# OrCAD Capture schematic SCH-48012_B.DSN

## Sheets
1 01 COVER: title: AUD-EXP-42448; rev: B; company: NXP Semiconductors; note: SCH-48012, PDF: SPF-48012; note: 6501 William Cannon Drive West; note: Austin, TX 78735-8598
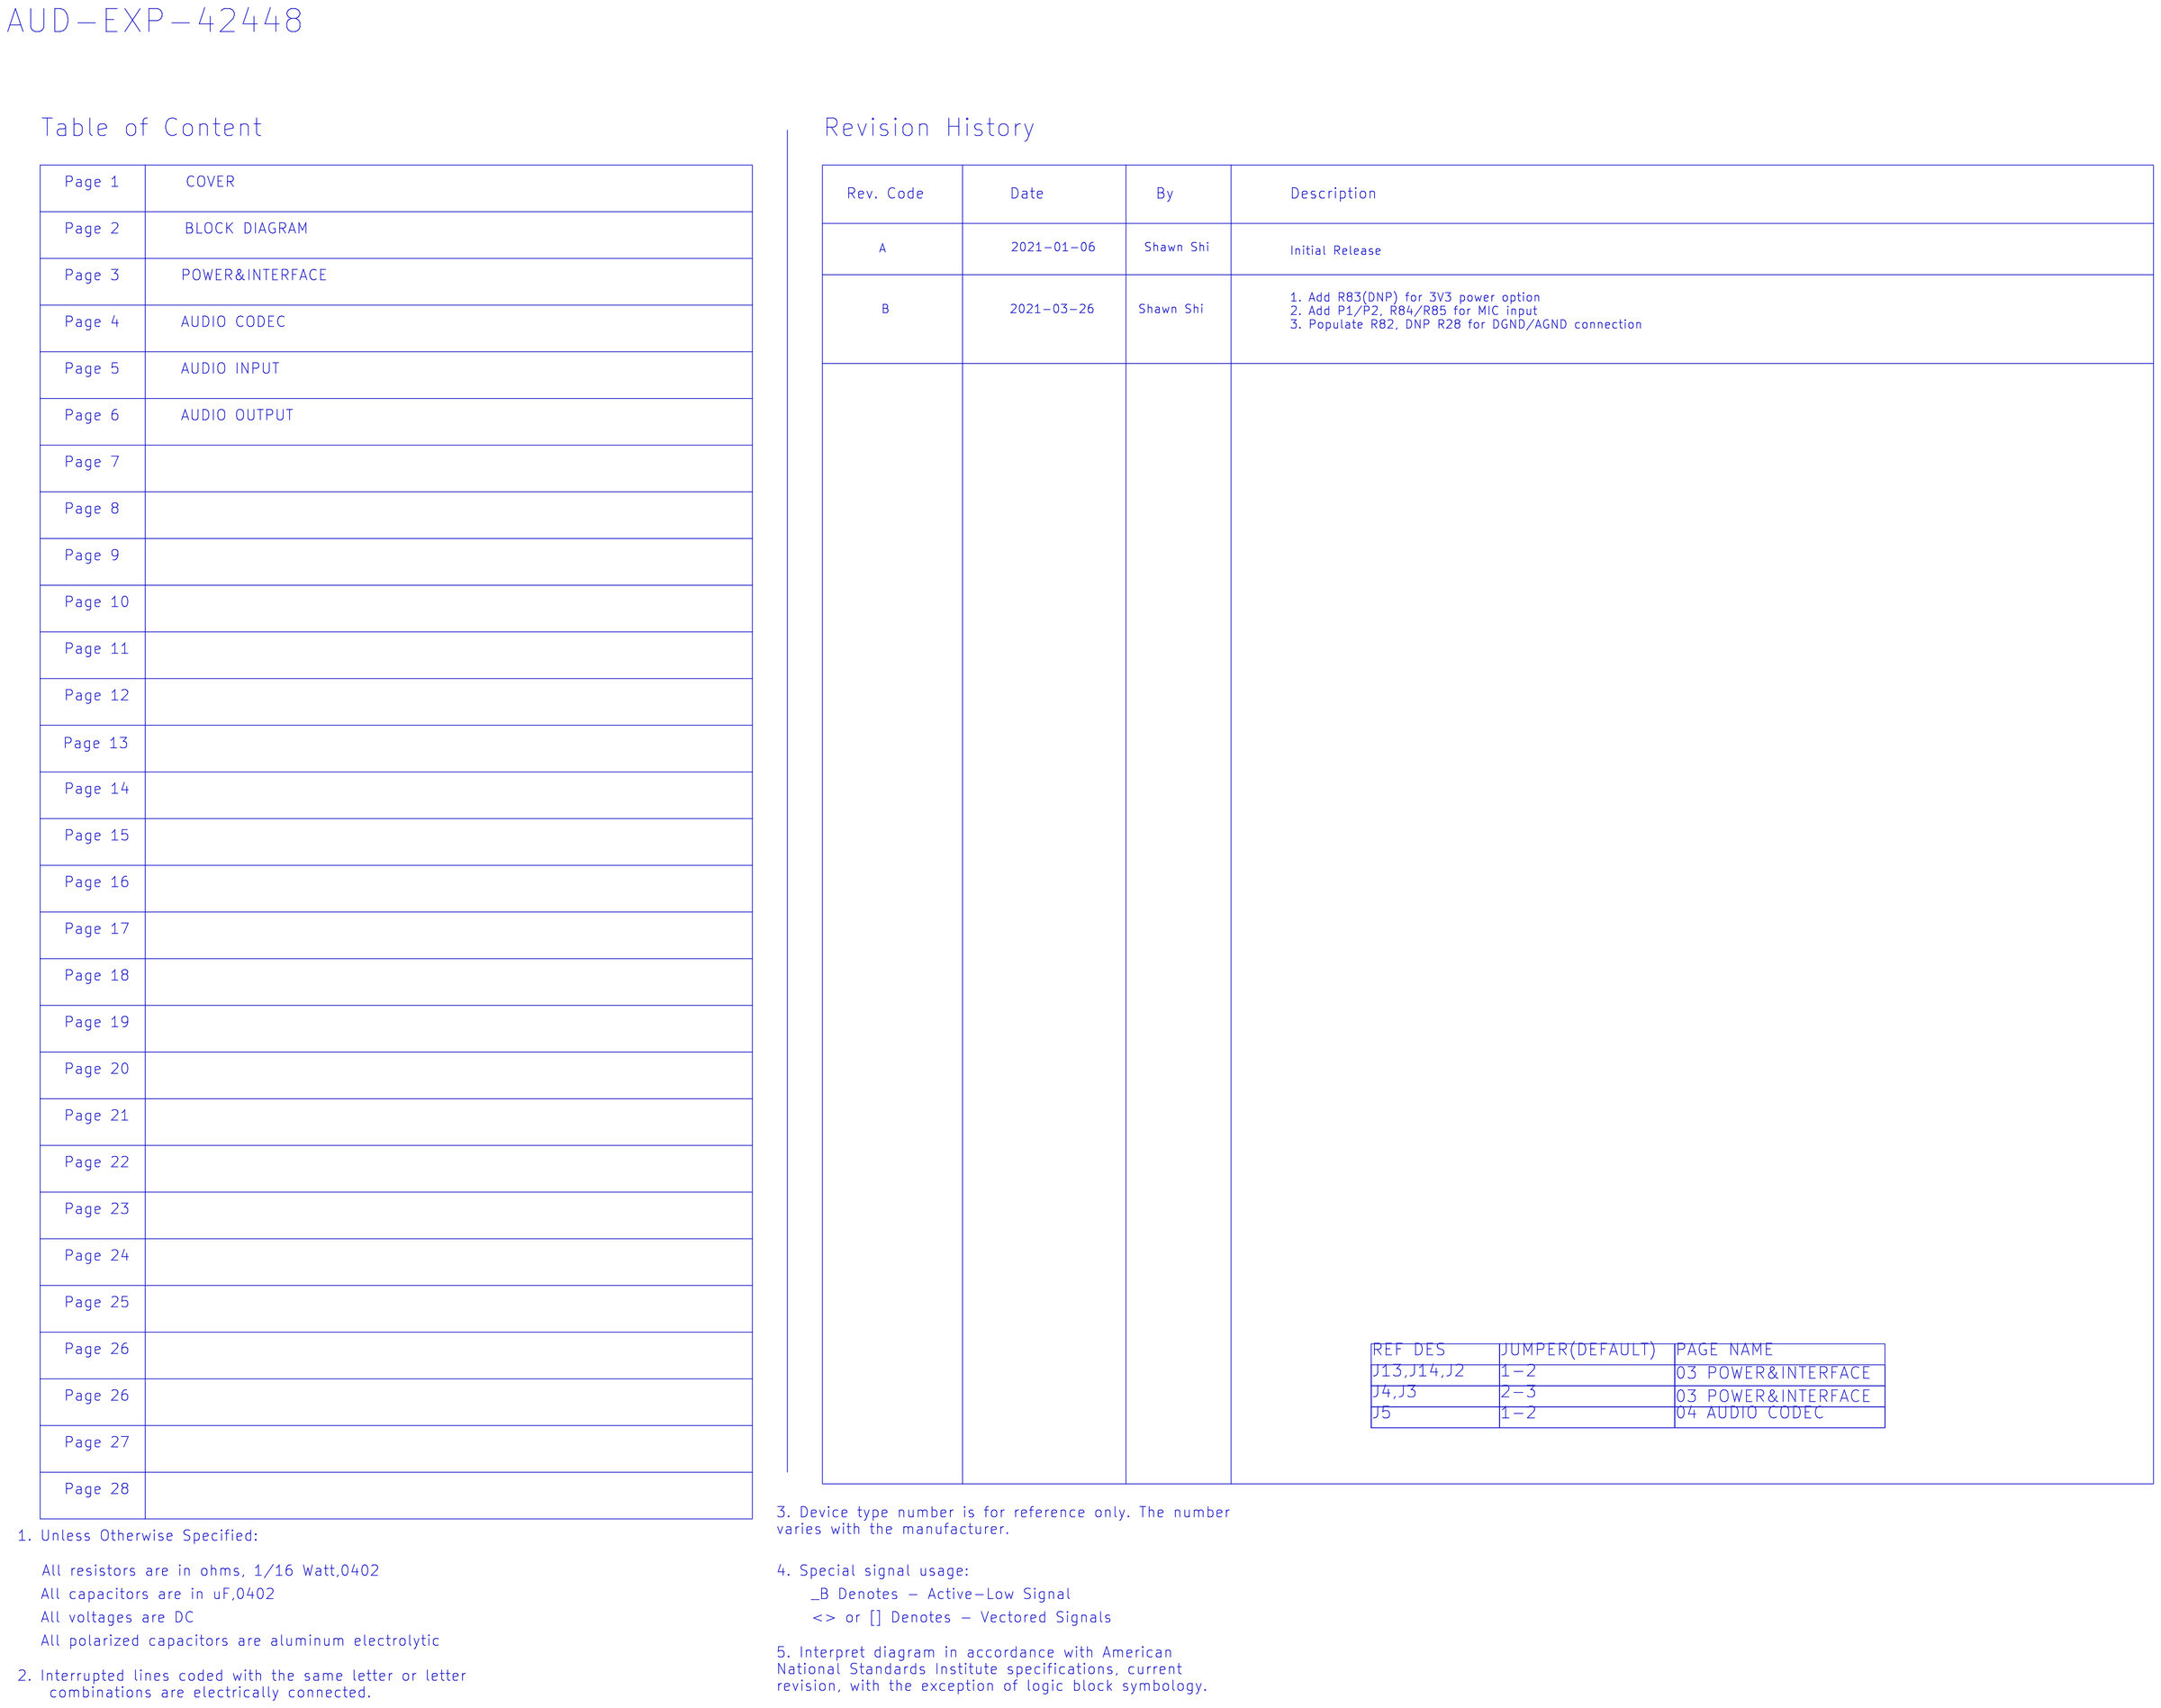
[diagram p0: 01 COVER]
2 02 BLOCK DIAGRAM
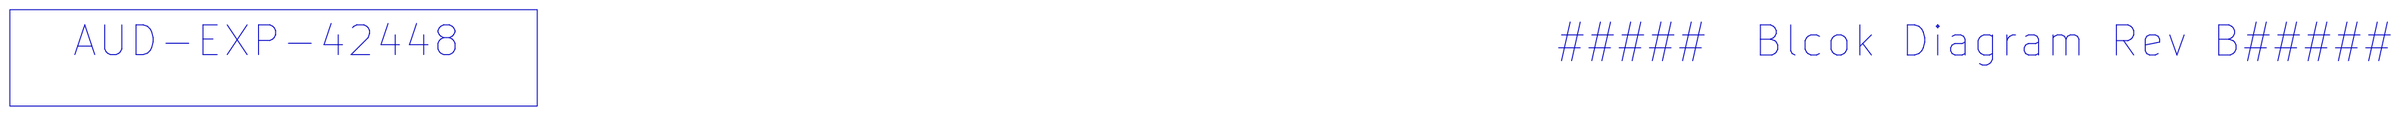
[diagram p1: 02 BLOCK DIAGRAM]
3 03 POWER&INTERFACE: size C
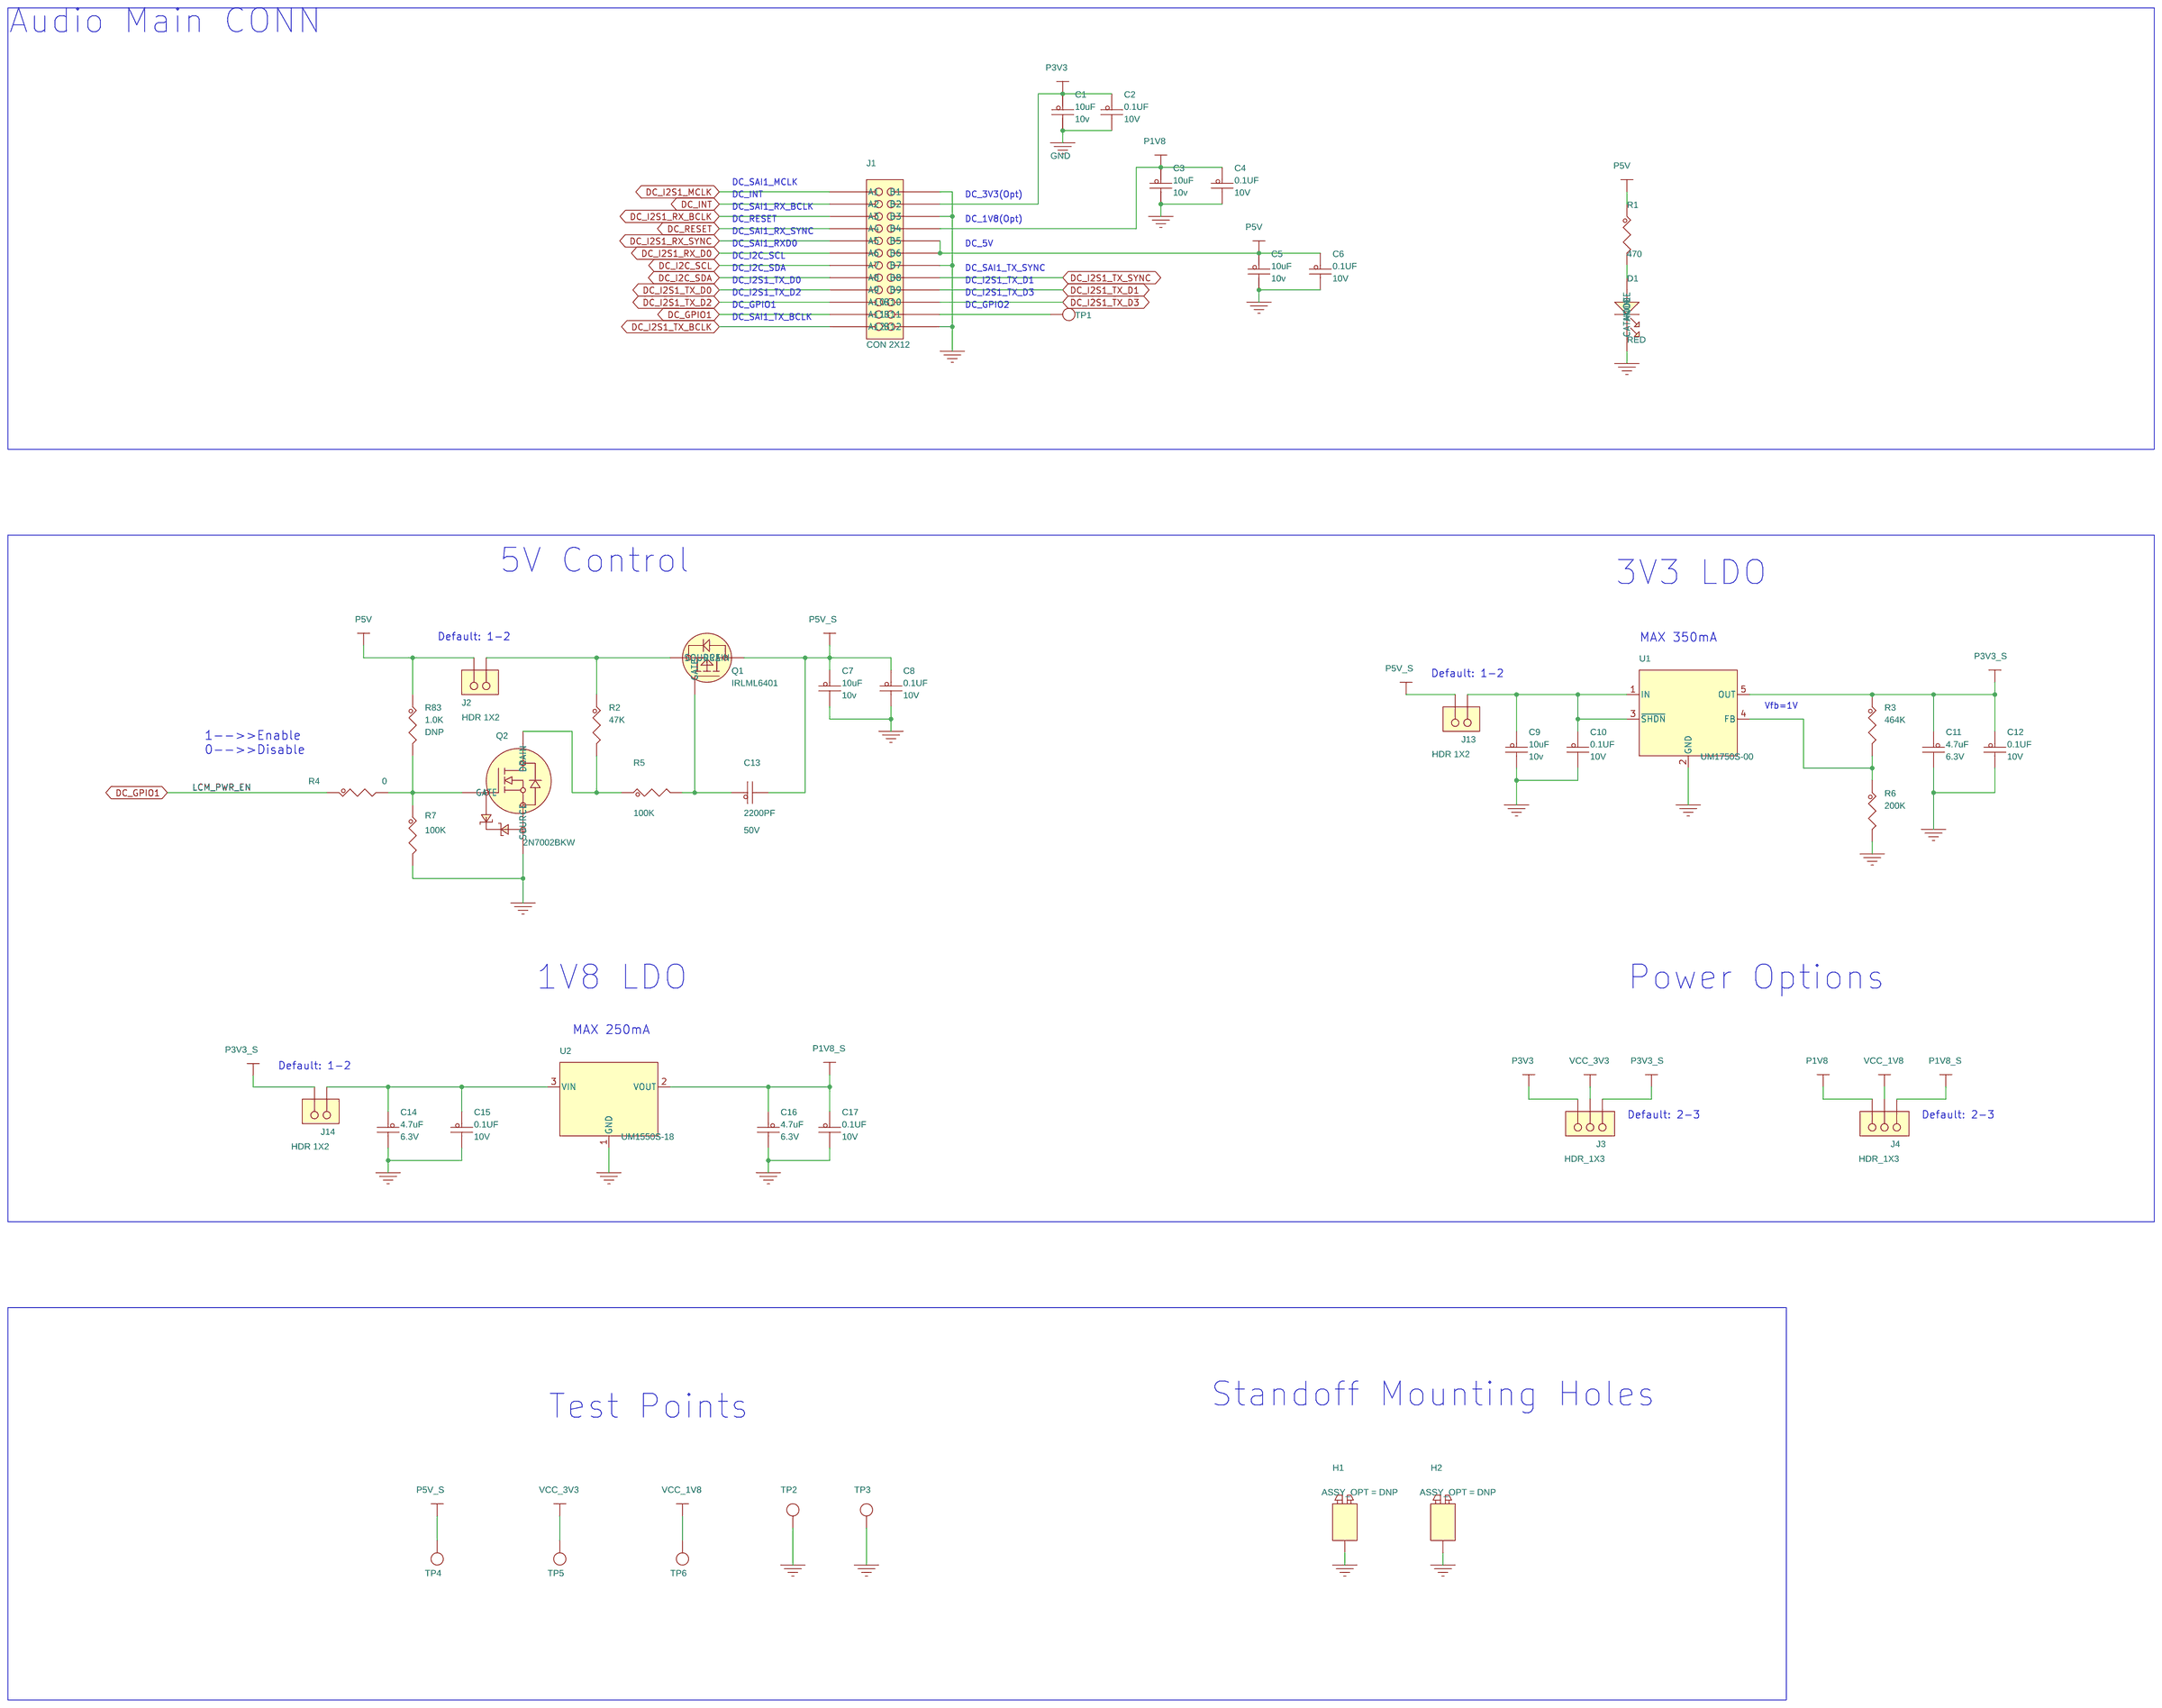
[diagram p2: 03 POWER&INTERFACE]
4 04 AUDIO CODEC: size C
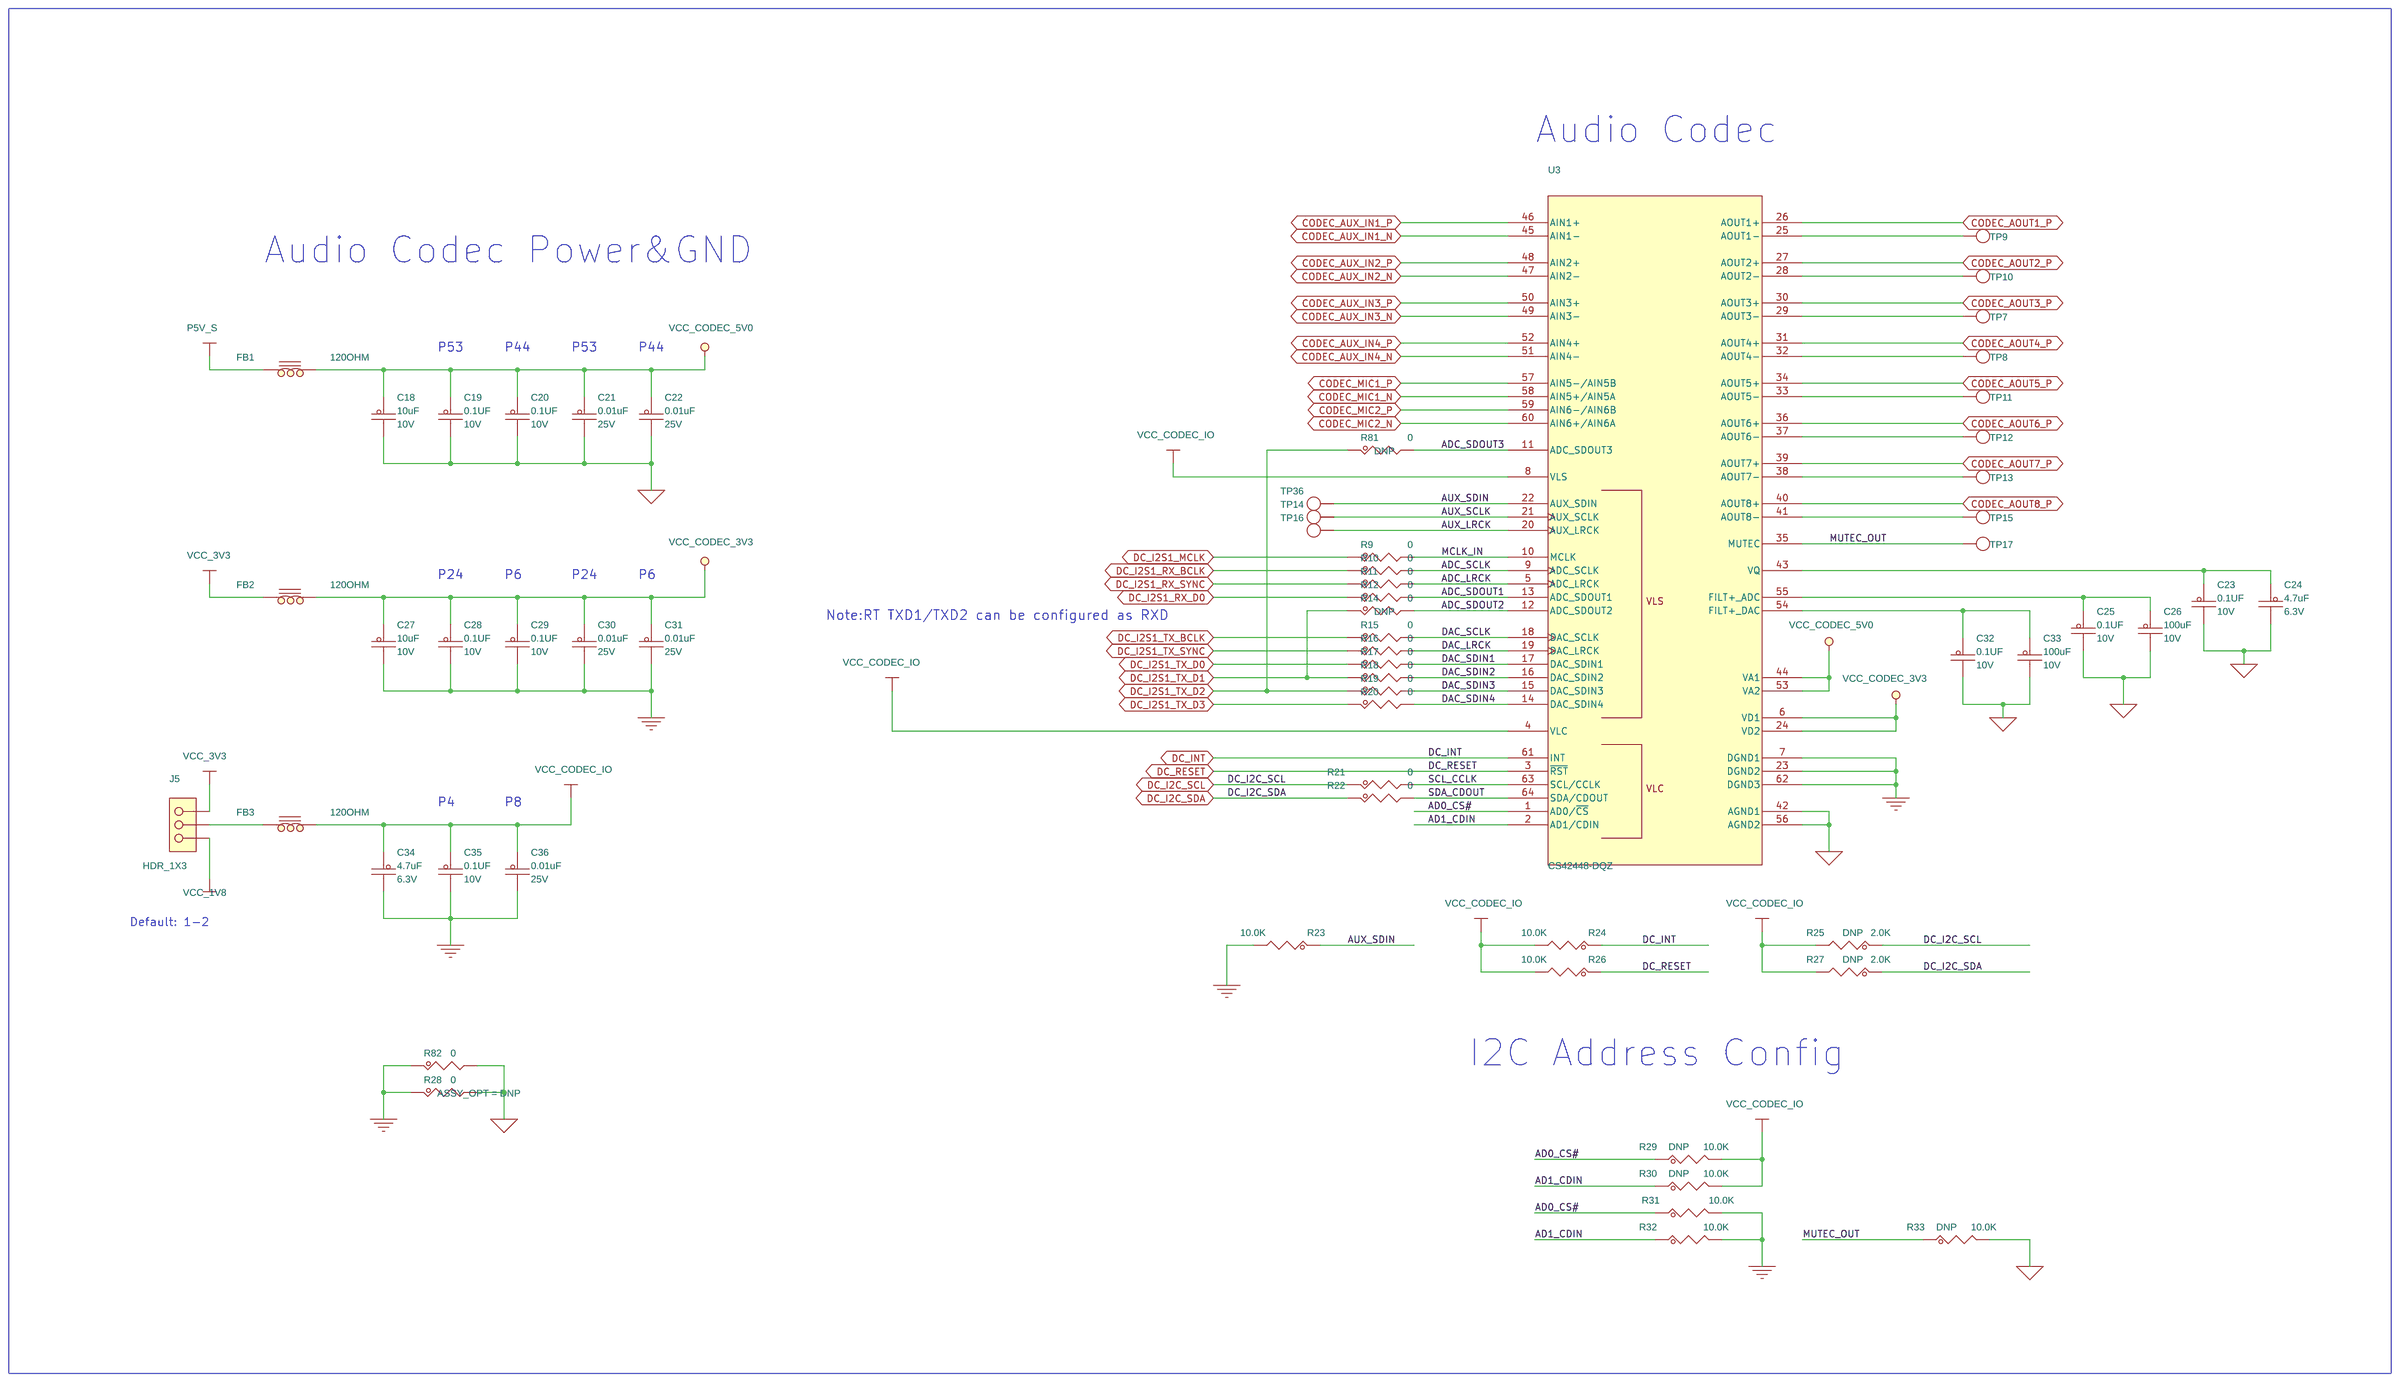
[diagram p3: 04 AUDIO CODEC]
5 05 AUDIO INPUT: size C
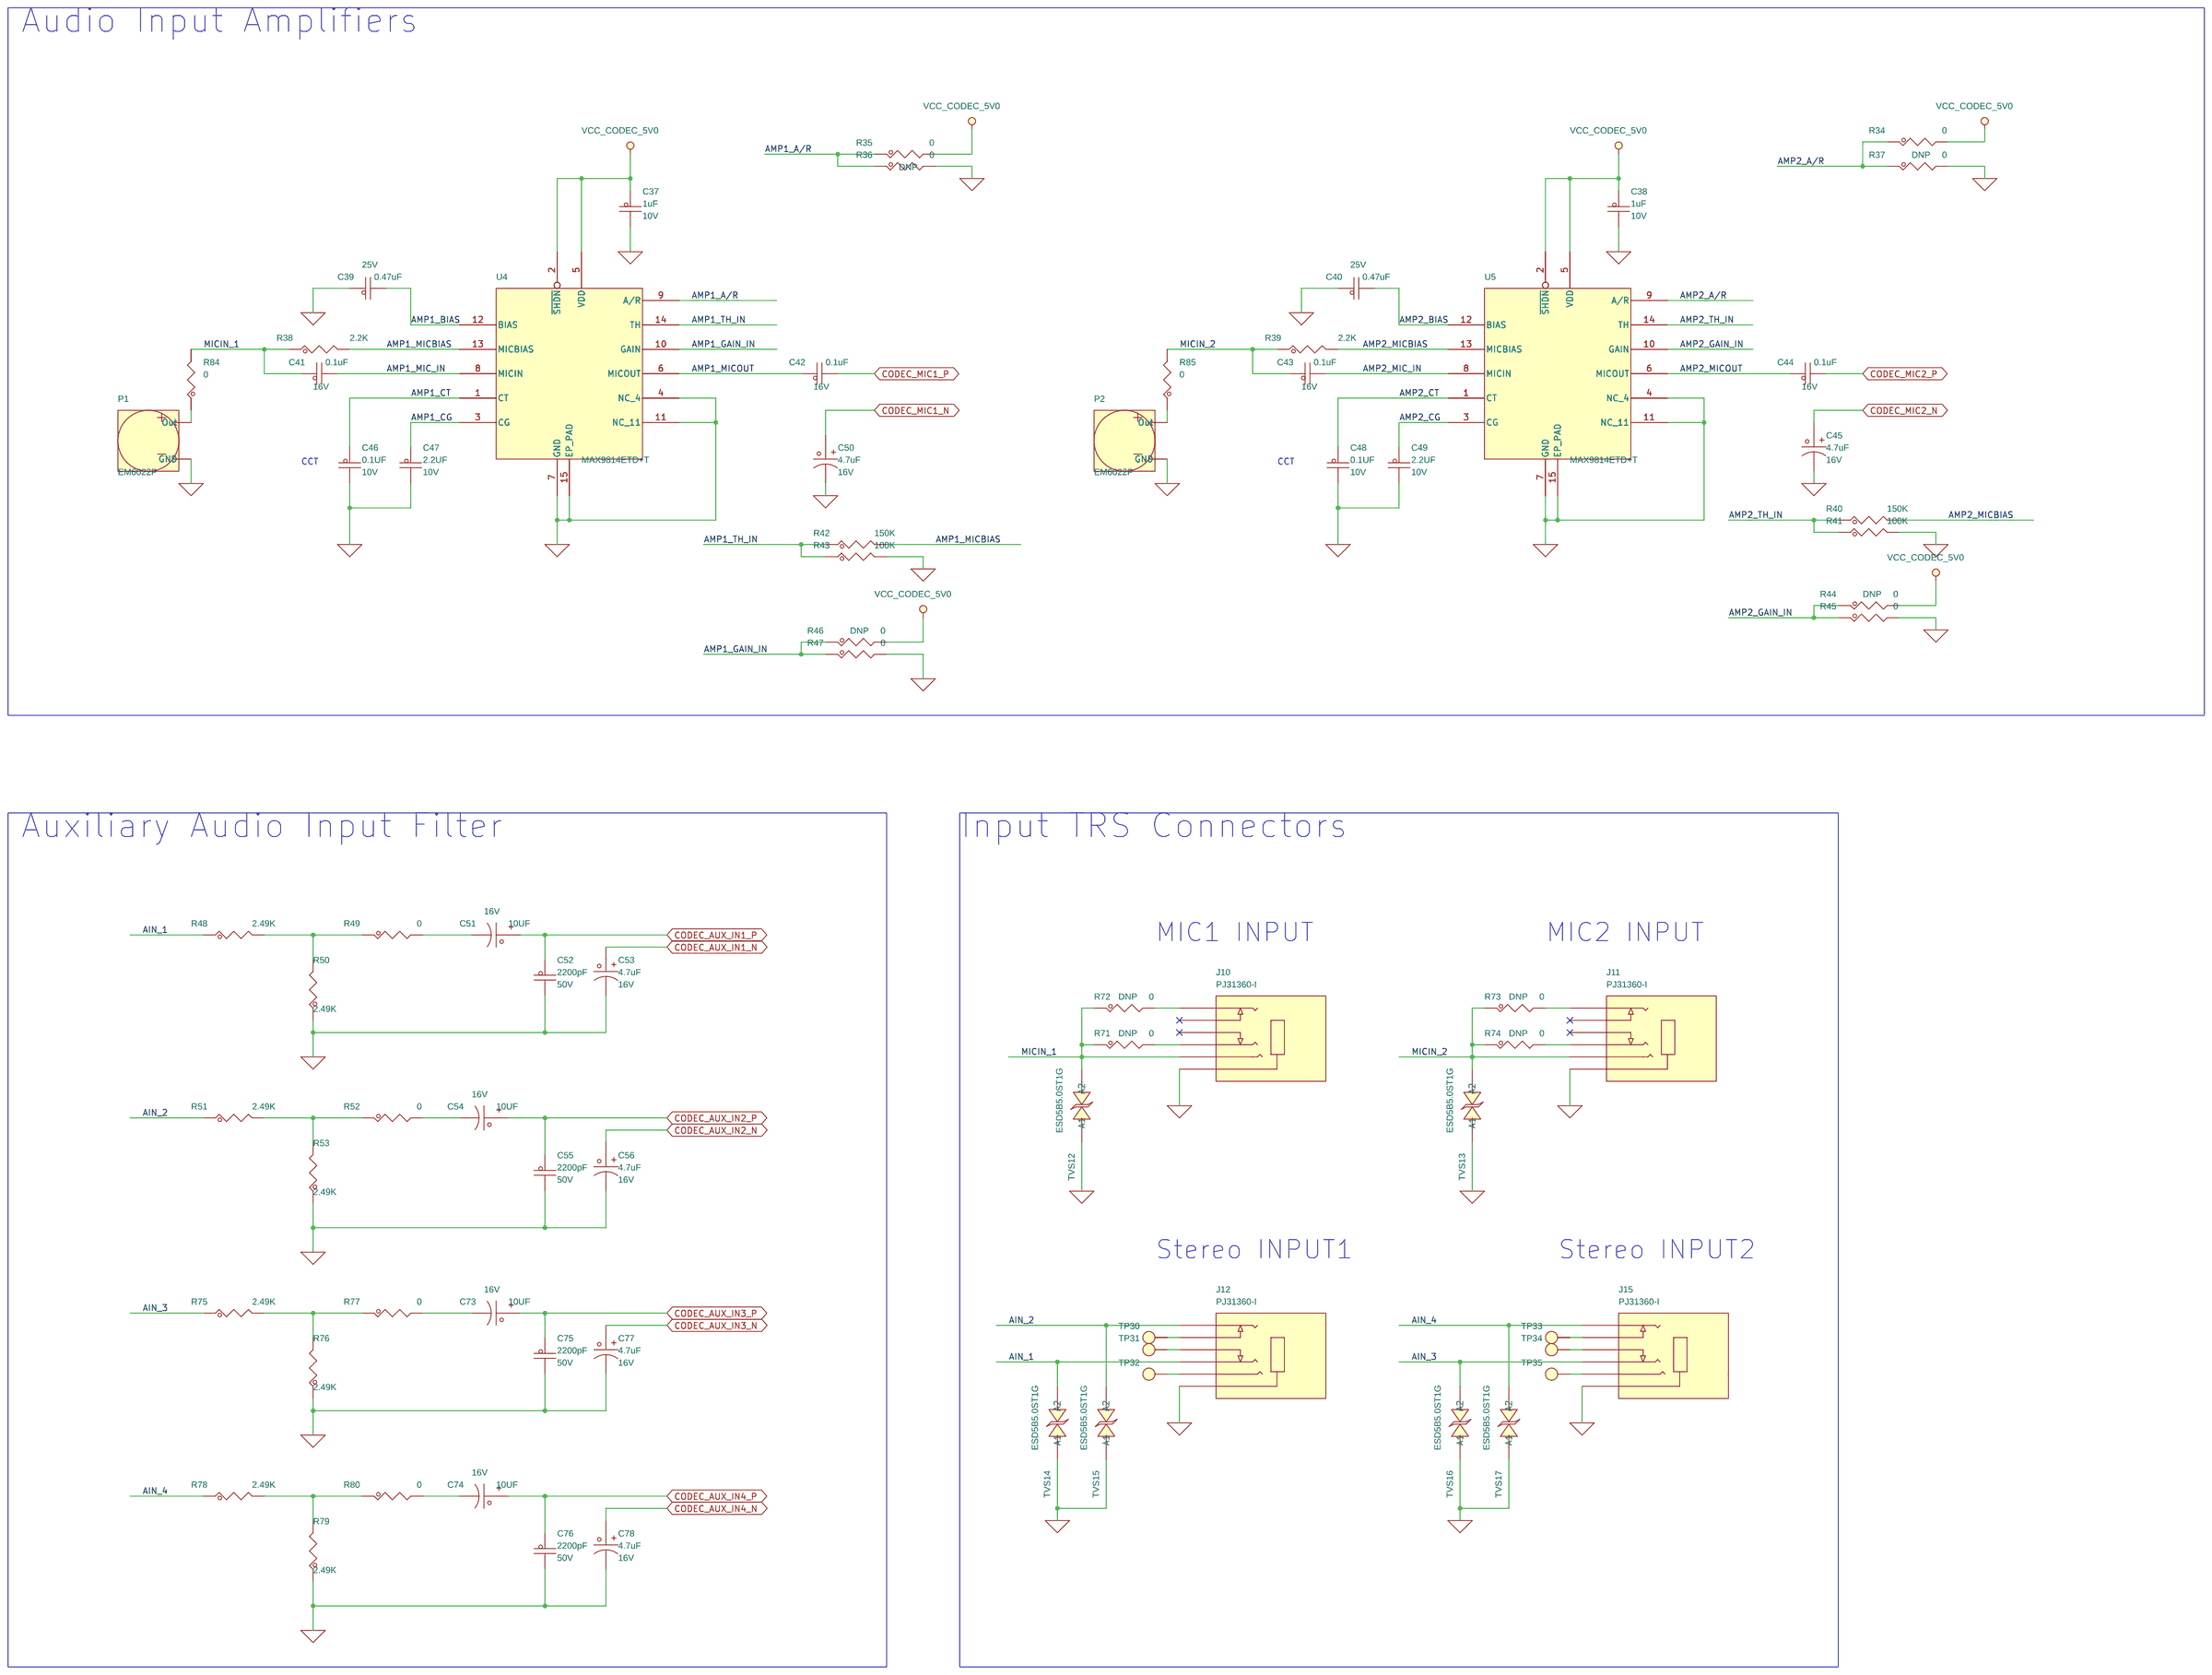
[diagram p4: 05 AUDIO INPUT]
6 06 AUDIO OUTPUT: size C
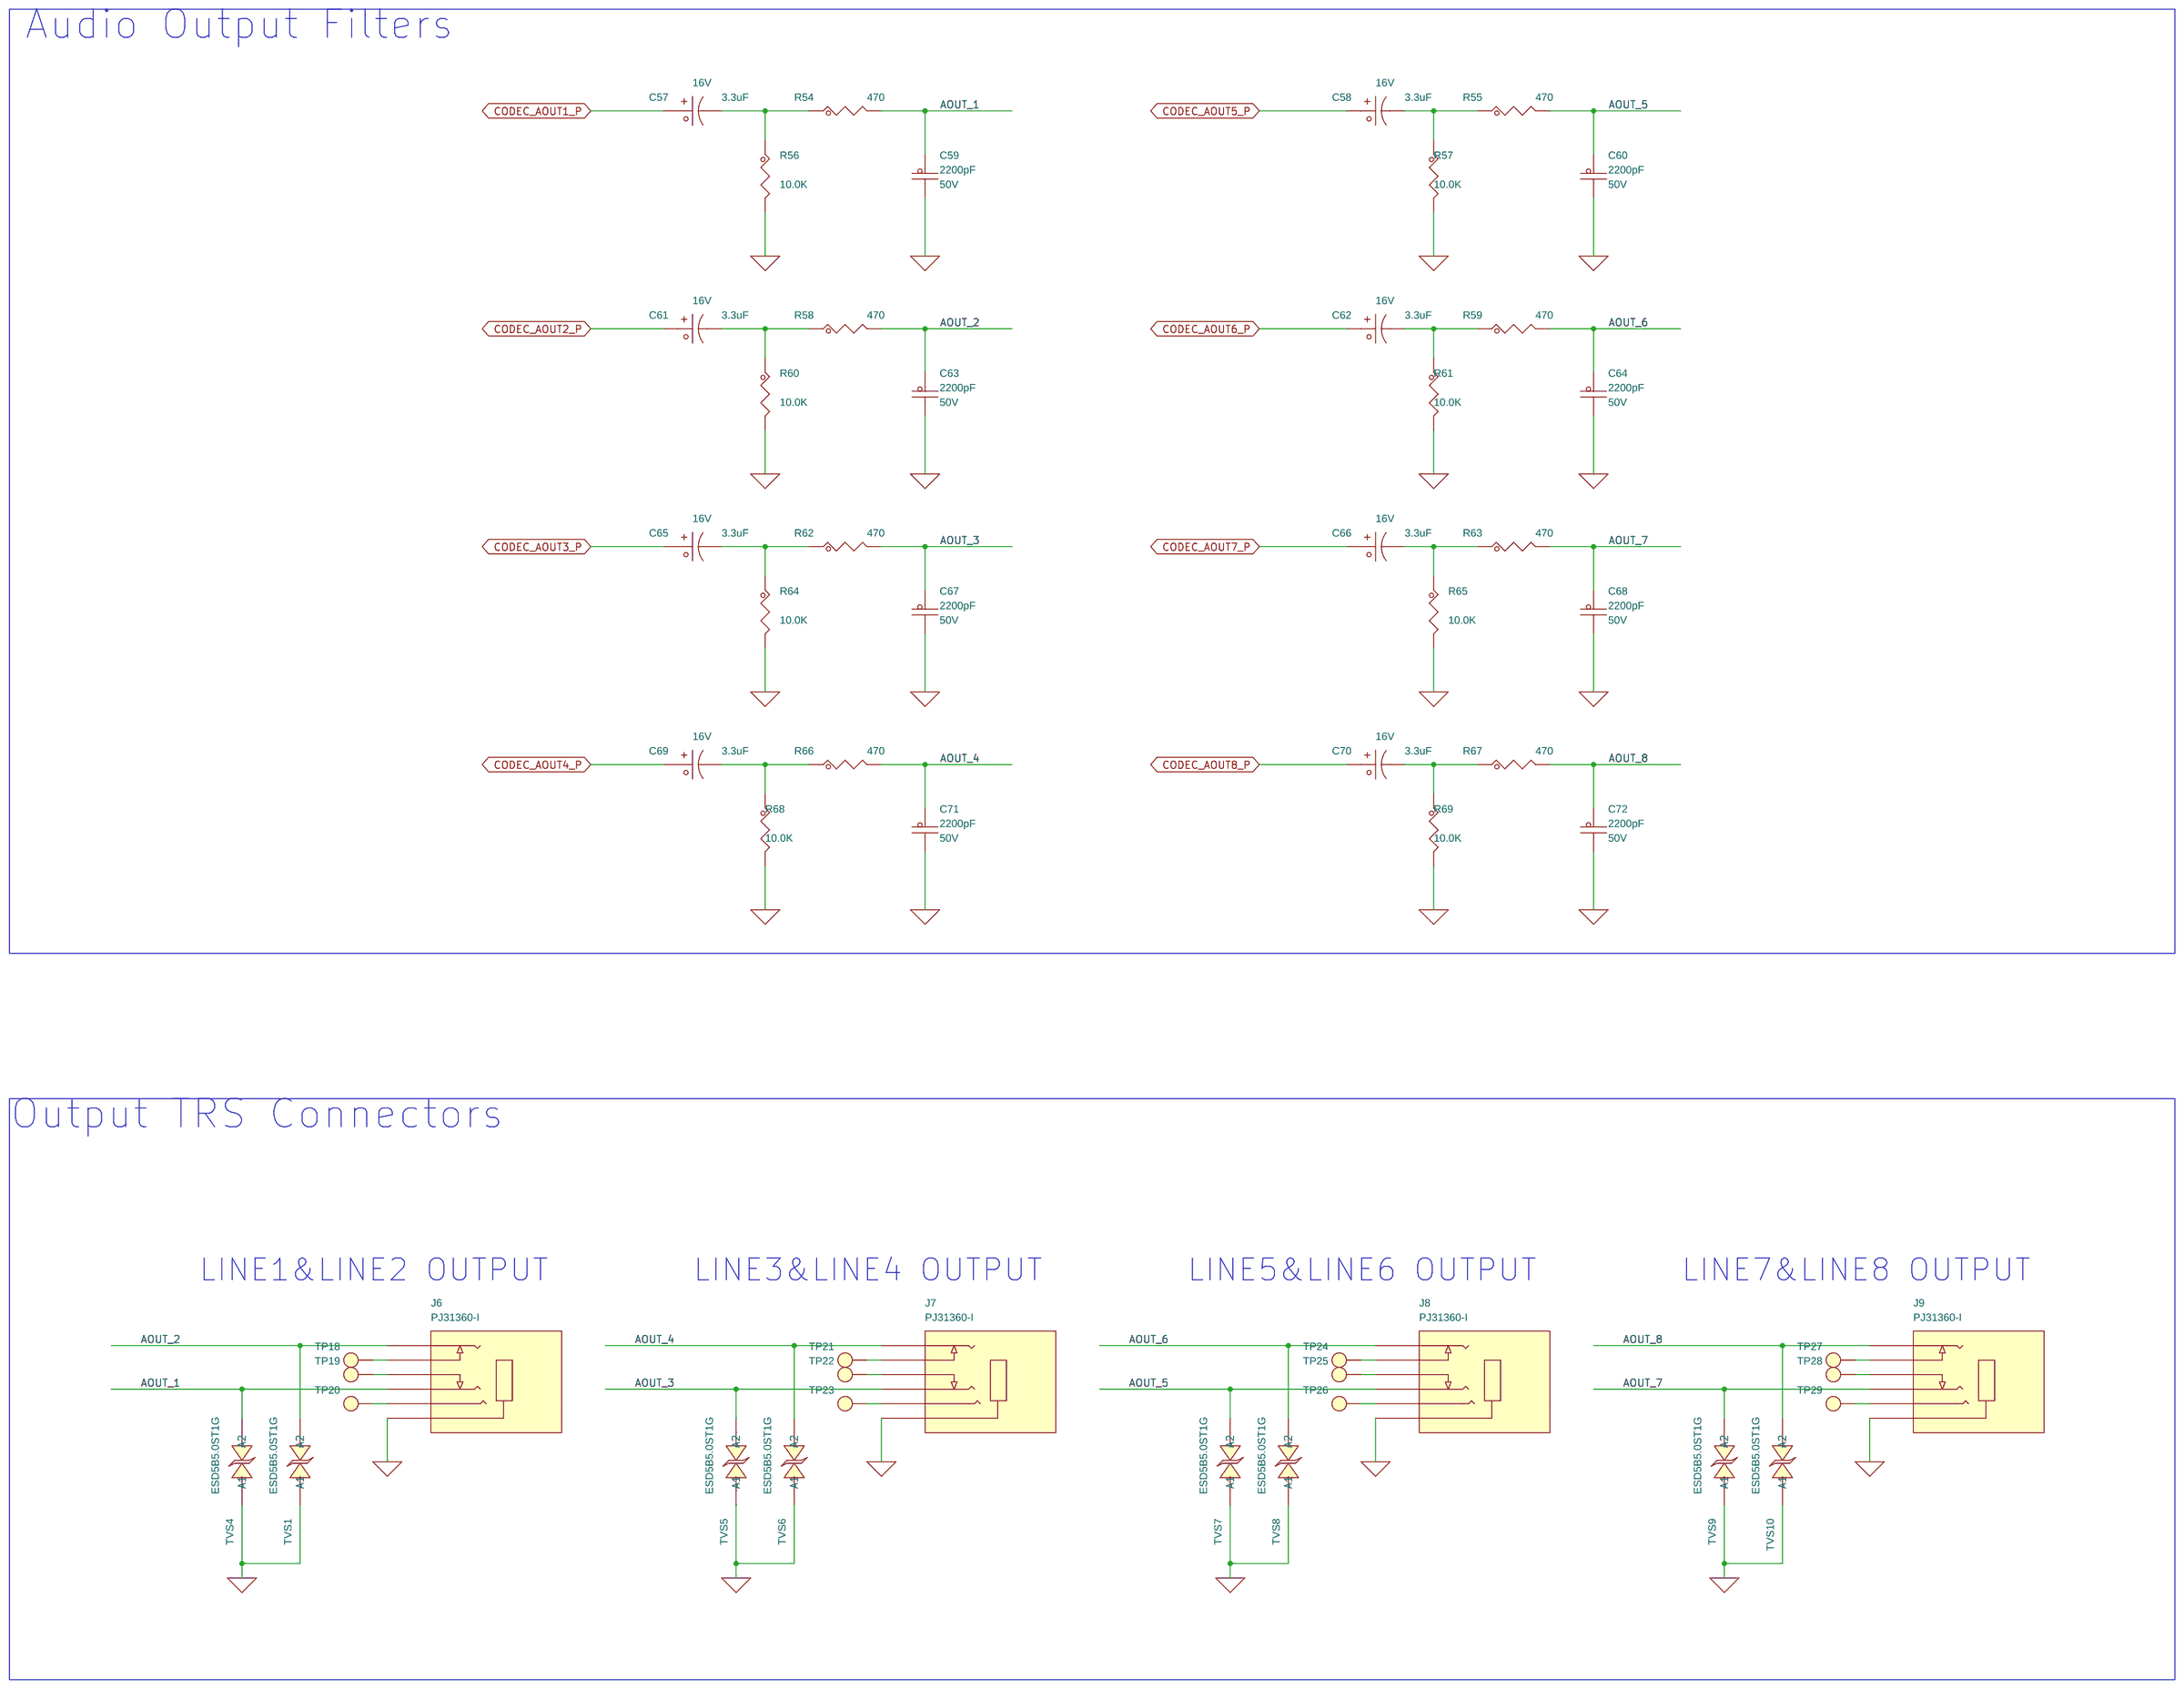
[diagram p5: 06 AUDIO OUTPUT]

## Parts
sheet 03 POWER&INTERFACE
C1  10uF  [CC0603_OV]
C2  0.1UF  [CC0402_25]
C3  10uF  [CC0603_OV]
C4  0.1UF  [CC0402_25]
C5  10uF  [CC0603_OV]
C6  0.1UF  [CC0402_25]
C7  10uF  [CC0603_OV]
C8  0.1UF  [CC0402_25]
C9  10uF  [CC0603_OV]
C10  0.1UF  [0402_CC]
C11  4.7uF  [0402_CC]
C12  0.1UF  [0402_CC]
C13  2200PF  [CC0402_25]
C14  4.7uF  [0402_CC]
C15  0.1UF  [0402_CC]
C16  4.7uF  [0402_CC]
C17  0.1UF  [0402_CC]
D1  RED  [LED_0603]
H1  .635" LONG  [spacer_139t]
H2  .635" LONG  [spacer_139t]
J1  CON 2X12  [con24_2mm_th]
J2  HDR 1X2  [HDR102]
J3  HDR_1X3  [HDR103]
J4  HDR_1X3  [HDR103]
J13  HDR 1X2  [HDR102]
J14  HDR 1X2  [HDR102]
Q1  IRLML6401  [sot-23]
Q2  2N7002BKW  [sc70_3]
R1  470  [RC0402_25]
R2  47K  [RC0402_25]
R3  464K  [RC0402_25]
R4  0  [RC0402_25]
R5  100K  [RC0402_25]
R6  200K  [RC0402_25]
R7  100K  [RC0402_25]
R83  1.0K  [RC0402_25]
TP1  TPAD_050  [TPAD_050]
TP2  TPAD_050  [TPAD_050]
TP3  TPAD_050  [TPAD_050]
TP4  TPAD_050  [TPAD_050]
TP5  TPAD_050  [TPAD_050]
TP6  TPAD_050  [TPAD_050]
U1  UM1750S-00  [sot23-5_a]
U2  UM1550S-18  [sot23-3-1p95]
sheet 04 AUDIO CODEC
C18  10uF  [CC0402_25]
C19  0.1UF  [0402_CC]
C20  0.1UF  [0402_CC]
C21  0.01uF  [0402_CC]
C22  0.01uF  [0402_CC]
C23  0.1UF  [0402_CC]
C24  4.7uF  [0402_CC]
C25  0.1UF  [0402_CC]
C26  100uF  [CC1206_OV]
C27  10uF  [CC0402_25]
C28  0.1UF  [0402_CC]
C29  0.1UF  [0402_CC]
C30  0.01uF  [0402_CC]
C31  0.01uF  [0402_CC]
C32  0.1UF  [0402_CC]
C33  100uF  [CC1206_OV]
C34  4.7uF  [0402_CC]
C35  0.1UF  [0402_CC]
C36  0.01uF  [0402_CC]
FB1  120OHM  [0603_CC]
FB2  120OHM  [0603_CC]
FB3  120OHM  [0603_CC]
J5  HDR_1X3  [HDR103]
R9  0  [RC0402_25]
R10  0  [RC0402_25]
R11  0  [RC0402_25]
R12  0  [RC0402_25]
R14  0  [RC0402_25]
R15  0  [RC0402_25]
R16  0  [RC0402_25]
R17  0  [RC0402_25]
R18  0  [RC0402_25]
R19  0  [RC0402_25]
R20  0  [RC0402_25]
R21  0  [RC0402_25]
R22  0  [RC0402_25]
R23  10.0K  [RC0402_25]
R24  10.0K  [RC0402_25]
R25  2.0K  [RC0402_25]
R26  10.0K  [RC0402_25]
R27  2.0K  [RC0402_25]
R28  0  [RC0402_25]
R29  10.0K  [RC0402_25]
R30  10.0K  [RC0402_25]
R31  10.0K  [RC0402_25]
R32  10.0K  [RC0402_25]
R33  10.0K  [RC0402_25]
R81  0  [RC0402_25]
R82  0  [RC0402_25]
TP7  TPAD_050  [TPAD_050]
TP8  TPAD_050  [TPAD_050]
TP9  TPAD_050  [TPAD_050]
TP10  TPAD_050  [TPAD_050]
TP11  TPAD_050  [TPAD_050]
TP12  TPAD_050  [TPAD_050]
TP13  TPAD_050  [TPAD_050]
TP14  TPAD_050  [TPAD_050]
TP15  TPAD_050  [TPAD_050]
TP16  TPAD_050  [TPAD_050]
TP17  TPAD_050  [TPAD_050]
TP36  TPAD_050  [TPAD_050]
U3  CS42448-DQZ  [lqfp64_0p5_10x10]
sheet 05 AUDIO INPUT
C37  1uF  [CC0402_25]
C38  1uF  [CC0402_25]
C39  0.47uF  [CC0603_OV]
C40  0.47uF  [CC0603_OV]
C41  0.1uF  [CC1210]
C42  0.1uF  [CC1210]
C43  0.1uF  [CC1210]
C44  0.1uF  [CC1210]
C45  4.7uF  [cce40x54]
C46  0.1UF  [0402_CC]
C47  2.2UF  [CC0402_25]
C48  0.1UF  [0402_CC]
C49  2.2UF  [CC0402_25]
C50  4.7uF  [cce40x54]
C51  10UF  [cce40x54]
C52  2200pF  [CC0402_25]
C53  4.7uF  [cce40x54]
C54  10UF  [cce40x54]
C55  2200pF  [CC0402_25]
C56  4.7uF  [cce40x54]
C73  10UF  [cce40x54]
C74  10UF  [cce40x54]
C75  2200pF  [CC0402_25]
C76  2200pF  [CC0402_25]
C77  4.7uF  [cce40x54]
C78  4.7uF  [cce40x54]
J10  PJ31360-I  [con6_audjack_ra_th]
J11  PJ31360-I  [con6_audjack_ra_th]
J12  PJ31360-I  [con6_audjack_ra_th]
J15  PJ31360-I  [con6_audjack_ra_th]
P1  EM6022P  [mic_WM-63PR]
P2  EM6022P  [mic_WM-63PR]
R34  0  [RC0402_25]
R35  0  [RC0402_25]
R36  0  [RC0402_25]
R37  0  [RC0402_25]
R38  2.2K  [RC0402_25]
R39  2.2K  [RC0402_25]
R40  150K  [RC0402_25]
R41  100K  [RC0402_25]
R42  150K  [RC0402_25]
R43  100K  [RC0402_25]
R44  0  [RC0402_25]
R45  0  [RC0402_25]
R46  0  [RC0402_25]
R47  0  [RC0402_25]
R48  2.49K  [RC0402_25]
R49  0  [RC0402_25]
R50  2.49K  [RC0402_25]
R51  2.49K  [RC0402_25]
R52  0  [RC0402_25]
R53  2.49K  [RC0402_25]
R71  0  [RC0402_25]
R72  0  [RC0402_25]
R73  0  [RC0402_25]
R74  0  [RC0402_25]
R75  2.49K  [RC0402_25]
R76  2.49K  [RC0402_25]
R77  0  [RC0402_25]
R78  2.49K  [RC0402_25]
R79  2.49K  [RC0402_25]
R80  0  [RC0402_25]
R84  0  [RC0402_25]
R85  0  [RC0402_25]
TP30  TP_35MIL  [testpoint_35mil]
TP31  TP_35MIL  [testpoint_35mil]
TP32  TP_35MIL  [testpoint_35mil]
TP33  TP_35MIL  [testpoint_35mil]
TP34  TP_35MIL  [testpoint_35mil]
TP35  TP_35MIL  [testpoint_35mil]
TVS12  ESD5B5.0ST1G  [diode2_sod523]
TVS13  ESD5B5.0ST1G  [diode2_sod523]
TVS14  ESD5B5.0ST1G  [diode2_sod523]
TVS15  ESD5B5.0ST1G  [diode2_sod523]
TVS16  ESD5B5.0ST1G  [diode2_sod523]
TVS17  ESD5B5.0ST1G  [diode2_sod523]
U4  MAX9814ETD+T  [tdfn14_0p4_3p1x3p1]
U5  MAX9814ETD+T  [tdfn14_0p4_3p1x3p1]
sheet 06 AUDIO OUTPUT
C57  3.3uF  [cc_a5]
C58  3.3uF  [cc_a5]
C59  2200pF  [CC0402_25]
C60  2200pF  [CC0402_25]
C61  3.3uF  [cc_a5]
C62  3.3uF  [cc_a5]
C63  2200pF  [CC0402_25]
C64  2200pF  [CC0402_25]
C65  3.3uF  [cc_a5]
C66  3.3uF  [cc_a5]
C67  2200pF  [CC0402_25]
C68  2200pF  [CC0402_25]
C69  3.3uF  [cc_a5]
C70  3.3uF  [cc_a5]
C71  2200pF  [CC0402_25]
C72  2200pF  [CC0402_25]
J6  PJ31360-I  [con6_audjack_ra_th]
J7  PJ31360-I  [con6_audjack_ra_th]
J8  PJ31360-I  [con6_audjack_ra_th]
J9  PJ31360-I  [con6_audjack_ra_th]
R54  470  [RC0402_25]
R55  470  [RC0402_25]
R56  10.0K  [RC0402_25]
R57  10.0K  [RC0402_25]
R58  470  [RC0402_25]
R59  470  [RC0402_25]
R60  10.0K  [RC0402_25]
R61  10.0K  [RC0402_25]
R62  470  [RC0402_25]
R63  470  [RC0402_25]
R64  10.0K  [RC0402_25]
R65  10.0K  [RC0402_25]
R66  470  [RC0402_25]
R67  470  [RC0402_25]
R68  10.0K  [RC0402_25]
R69  10.0K  [RC0402_25]
TP18  TP_35MIL  [testpoint_35mil]
TP19  TP_35MIL  [testpoint_35mil]
TP20  TP_35MIL  [testpoint_35mil]
TP21  TP_35MIL  [testpoint_35mil]
TP22  TP_35MIL  [testpoint_35mil]
TP23  TP_35MIL  [testpoint_35mil]
TP24  TP_35MIL  [testpoint_35mil]
TP25  TP_35MIL  [testpoint_35mil]
TP26  TP_35MIL  [testpoint_35mil]
TP27  TP_35MIL  [testpoint_35mil]
TP28  TP_35MIL  [testpoint_35mil]
TP29  TP_35MIL  [testpoint_35mil]
TVS1  ESD5B5.0ST1G  [diode2_sod523]
TVS4  ESD5B5.0ST1G  [diode2_sod523]
TVS5  ESD5B5.0ST1G  [diode2_sod523]
TVS6  ESD5B5.0ST1G  [diode2_sod523]
TVS7  ESD5B5.0ST1G  [diode2_sod523]
TVS8  ESD5B5.0ST1G  [diode2_sod523]
TVS9  ESD5B5.0ST1G  [diode2_sod523]
TVS10  ESD5B5.0ST1G  [diode2_sod523]

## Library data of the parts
C1 C3 C5 C7 C9 = CAP_NP: CAP CER 10UF 10V 10% X5R 0603; AGILE_PN: 150-78675; CAD_APPROVED: Yes; FPLIST: CC0603_OV,CC0603,0603_CC; HEIGHT: 1.016MM; MFG_NAME01: MURATA; MFG_PN01: GRM188R61A106KE69D; ROHS: Yes; Temp_Range: -55°C ~ 85°C; Tolerance: 10%; VOLTAGE: 10v
C2 C4 C6 C8 C10 C12 C15 C17 C19 C20 C23 C25 C28 C29 C32 C35 C46 C48 = CAP_NP: CAP CER 0.1UF 10V 10% X5R 0402; AGILE_PN: 150-75634; CAD_APPROVED: Yes; FPLIST: CC0402_25,CC0402_HD,0402_CC; HEIGHT: 0.64MM; MFG_NAME01: YAGEO AMERICA; MFG_PN01: CC0402KRX5R6BB104; ROHS: Yes; Tolerance: 10%; VOLTAGE: 10V
C11 C14 C16 C24 C34 = CAP_NP: CAP CER 4.7UF 6.3V 20% X5R 0402; AGILE_PN: 150-78463; CAD_APPROVED: Yes; FPLIST: CC0402_25,CC0402_HD,0402_CC; HEIGHT: 0.65MM; MFG_NAME01: TDK; MFG_PN01: C1005X5R0J475M050BC; ROHS: Yes; Tolerance: 20%; VOLTAGE: 6.3V; voltage rating: 6.3V
C13 = CAP_NP: CAP CER 2200PF 50V 10%  X7R 0402; AGILE_PN: 150-75600; CAD_APPROVED: Yes; FPLIST: CC0402_25,CC0402_HD,0402_CC; HEIGHT: 0.55MM; MFG_NAME01: AVX; MFG_PN01: 04025C222KAT2A; ROHS: Yes; Tolerance: 10%; VOLTAGE: 50V
D1 = LED: LED RED SGL 20MA 0603; AGILE_PN: 370-76632; CAD_APPROVED: Yes; EN: 106-4-00247; HEIGHT: 0.45MM; MFG_NAME01: LITE ON; MFG_PN01: LTST-C193KRKT-5A; ROHS: Yes
H1 H2 = SPACER: FASTENER, STANDOFF 4.5MMX3.53XM3.0X0.5 ROUND THR .635"L BRASS; AGILE_PN: 280-76498; ASSY_OPT: DNP; CAD_APPROVED: Yes; HEIGHT: 16.13MM; MFG_NAME01: UNICORP; MFG_PN01: MSS251-R-1-A-16; ROHS: Yes
J1 = CONN_HDR_12X2: CON 2X12 SKT TH 2MM CTR 179H AU 94L; AGILE_PN: 210-82748; CAD_APPROVED: Yes; HEIGHT: 4.55 MM; MFG_NAME01: ANYTRONIC CORPORATION LIMITED; MFG_PN01: 08103S3 2411#6T-29LF; ROHS: Yes
J2 J13 J14 = CONN_HDR_2X1: HDR 1X2 TH 100MIL SP 339H AU 98L; AGILE_PN: 210-81490; CAD_APPROVED: Yes; HEIGHT: 8.59MM; Jumper(Default): 1-2; MFG_NAME01: ANYTRONIC CORPORATION LIMITED; MFG_PN01: 0901S0202011N9T-31RF; ROHS: Yes; Temp_Range: -55°C to +105°C
J3 J4 = CONN_HDR_3X1: HDR 1X3 TH 100MIL SP 338H AU 98L; AGILE_PN: 210-81491; CAD_APPROVED: Yes; HEIGHT: 8.59MM; Jumper(Default): 2-3; MFG_NAME01: ANYTRONIC CORPORATION LIMITED; MFG_PN01: 0901S0203011N9T-31RF; ROHS: Yes; Temp_Range: -55°C to +105°C
Q1 = MOSFET_P: TRAN PMOS PWR 12V 4.3A SOT23; AGILE_PN: 480-77718; CAD_APPROVED: Yes; HEIGHT: 1.12MM; MFG_NAME01: INTERNATIONAL RECTIFIER; MFG_PN01: IRLML6401TRPBF; ROHS: Yes
Q2 = NMOS_2N7002BKW_3P: TRAN NMOS 310mA 60V AEC-Q101 SOT323; AGILE_PN: 480-79600; CAD_APPROVED: Yes; HEIGHT: 1.1MM; MFG_NAME01: NEXPERIA; MFG_PN01: 2N7002BKW,115; ROHS: Yes
R1 R54 R55 R58 R59 R62 R63 R66 R67 = RES: RES MF 470 OHM 1/16W 1% 0402; AGILE_PN: 470-76469; CAD_APPROVED: Yes; EN: 101-1-03571; FPLIST: RC0402_25,RC0402_HD,0402_CC; HEIGHT: 0.4 MM; MFG_NAME01: THYE MING TECH CO LTD; MFG_PN01: CR-02FL6--470R; ROHS: Yes; Tolerance: 1%
R2 = RES: RES MF 47K  1/16W 1% AEC-Q200 0402; AGILE_PN: 470-80702; CAD_APPROVED: Yes; FPLIST: RC0402_25,RC0402_HD,0402_CC; HEIGHT: 0.40 MM; MFG_NAME01: VISHAY INTERTECHNOLOGY; MFG_PN01: CRCW040247K0FKED; ROHS: Yes; Tolerance: 1%
R3 = RES: RES MF 464K 1/10W 1% AEC-Q200 0402; AGILE_PN: 470-31135; CAD_APPROVED: Yes; FPLIST: RC0402_25,RC0402_HD,0402_CC; HEIGHT: 0.40 MM; MFG_NAME01: KOA SPEER; MFG_PN01: RK73H1ETTP4643F; ROHS: Yes; Temp_Range: -55C to +155C; Tolerance: 1%
R4 R9-R12 R15-R22 R34 R35 R45 R47 R49 R52 R77 R80 R82 = RES: RES MF ZERO OHM 1/16W 5% 0402; AGILE_PN: 470-75394; CAD_APPROVED: Yes; EN: 101-1-04000; FPLIST: RC0402_25,RC0402_HD,RC0402_X2,0402_CC; HEIGHT: 0.45 MM; MFG_NAME01: ROHM; MFG_PN01: MCR01MZPJ000; ROHS: Yes; SIGNAL_MODEL: RES_RC0402_25_DISCRETE_470-7539_0; TOL: 5%; Tolerance: 5%
R5 R7 R41 R43 = RES: RES MF 100K 1/16W 5% 0402; AGILE_PN: 470-75597; CAD_APPROVED: Yes; EN: 101-1-02817; FPLIST: RC0402_25,RC0402_HD,0402_CC; HEIGHT: 0.40 MM; MFG_NAME01: KOA SPEER; MFG_PN01: RK73B1ETTP104J; ROHS: Yes; Tolerance: 5%
R6 = RES: RES MF 200K 1/10W 1% AEC-Q200 0402; AGILE_PN: 470-31093; CAD_APPROVED: Yes; FPLIST: RC0402_25,RC0402_HD,0402_CC; HEIGHT: 0.40 MM; MFG_NAME01: KOA SPEER; MFG_PN01: RK73H1ETTP2003F; ROHS: Yes; Temp_Range: -55C to +155C; Tolerance: 1%
R83 = RES: RES MF 1.0K 1/10W 1% 0402; AGILE_PN: 470-80531; ASSY_OPT: DNP; CAD_APPROVED: Yes; FPLIST: RC0402_25,RC0402_HD,RC0402_X2,0402_CC; HEIGHT: 0.4MM; MFG_NAME01: PANASONIC; MFG_PN01: ERJ-2RKF1001X; ROHS: Yes; Temp Range: –55 °C to +155 °C; Tolerance: 1%
TP1-TP17 TP36 = TESTLOOP: TEST POINT PAD 50MIL DIA SMT, NO PART TO ORDER; AGILE_PN: 211-76644; CAD_APPROVED: Yes; HEIGHT: 0.1MM; MFG_NAME01: NOTACOMPONENT; MFG_PN01: NOTACOMPONENT; ROHS: Yes
U1 = UM1750S-00_5P: IC VREG LDO ADJ 1-5V 350mA 2.5-6V SOT23-5; AGILE_PN: 315-80554; CAD_APPROVED: Yes; HEIGHT: 1.25MM; MFG_NAME01: Union Semiconductor, Inc; ROHS: Yes
U2 = MCP1700: IC LIN VREG LDO 1.8V 250MA 1.8-8V SOT23-3; AGILE_PN: 315-81422; CAD_APPROVED: Yes; HEIGHT: 1.4MM; MFG_NAME01: Union Semiconductor, Inc; ROHS: Yes
C18 C27 = CAP_NP: CAP CER 10uF 10V 20% X5R 0402; AGILE_PN: 150-79255; CAD_APPROVED: Yes; EN: 102-1-01803; FPLIST: CC0402_25,CC0402_HD,0402_CC; HEIGHT: 0.7MM; MFG_NAME01: SAMSUNG; MFG_PN01: CL05A106MP5NUNC; ROHS: Yes; Tolerance: 20%; VOLTAGE: 10V
C21 C22 C30 C31 C36 = CAP_NP: CAP CER 0.01UF 25V 10% X7R 0402; AGILE_PN: 150-75183; CAD_APPROVED: Yes; EN: 102-1-00027; FPLIST: CC0402_25,CC0402_HD,0402_CC; HEIGHT: 0.635mm; MFG_NAME01: AVX; MFG_PN01: 04023C103KAT2A; ROHS: Yes; TOL: 10%; Tolerance: 10%; VOLTAGE: 25V
C26 C33 = CAP_NP: CAP CER 100uF 10V 20% X5R 1206; AGILE_PN: 150-78880; CAD_APPROVED: Yes; EN: 102-1-01735; FPLIST: CC1206_OV,CC1206,1206_CC; HEIGHT: 1.9MM; MFG_NAME01: TDK; MFG_PN01: C3216X5R1A107M160AC; ROHS: Yes; Tolerance: 20%; VOLTAGE: 10V
FB1-FB3 = BEAD_0: IND FER BEAD 120OHM@100MHZ 2A 25% 0603; AGILE_PN: 180-30008; CAD_APPROVED: Yes; EN: 104-1-00022; FPLIST: IND_0603,0603_CC; HEIGHT: 0.95MM; MFG_NAME01: MURATA; MFG_PN01: BLM18PG121SH1; PART_TYPE: FERRITE; PRIORITY_PN: 024-00067; ROHS: Yes; ROOM: RGMII_PHY; TOL: 25%; Tolerance: 25%
J5 = CONN_HDR_3X1: HDR 1X3 TH 100MIL SP 338H AU 98L; AGILE_PN: 210-81491; CAD_APPROVED: Yes; HEIGHT: 8.59MM; Jumper(Default): 1-2; MFG_NAME01: ANYTRONIC CORPORATION LIMITED; MFG_PN01: 0901S0203011N9T-31RF; ROHS: Yes; Temp_Range: -55°C to +105°C
R14 R28 R36 R37 R44 R46 R71-R74 R81 = RES: RES MF ZERO OHM 1/16W 5% 0402; AGILE_PN: 470-75394; ASSY_OPT: DNP; CAD_APPROVED: Yes; EN: 101-1-04000; FPLIST: RC0402_25,RC0402_HD,RC0402_X2,0402_CC; HEIGHT: 0.45 MM; MFG_NAME01: ROHM; MFG_PN01: MCR01MZPJ000; ROHS: Yes; SIGNAL_MODEL: RES_RC0402_25_DISCRETE_470-7539_0; TOL: 5%; Tolerance: 5%
R23 R24 R26 R31 R32 R56 R57 R60 R61 R64 R65 R68 R69 = RES: RES MF 10.0K 1/16W 1% 0402; AGILE_PN: 470-80574; CAD_APPROVED: Yes; EN: 101-1-00389; FPLIST: RC0402_25,RC0402_HD,0402_CC; HEIGHT: 0.4MM; MFG_NAME01: WALSIN TECHNOLOGY CORP.; MFG_PN01: WR04X1002FTL; ROHS: Yes; Tolerance: 1%
R25 R27 = RES: RES MF 2.0K 1/16W 1% 0402; AGILE_PN: 470-75356; ASSY_OPT: DNP; CAD_APPROVED: Yes; EN: 101-1-00322; FPLIST: RC0402_25,RC0402_HD,0402_CC; HEIGHT: 0.4mm; MFG_NAME01: BOURNS; MFG_PN01: CR0402-FX-2001GLF; ROHS: Yes; Tolerance: 1%
R29 R30 R33 = RES: RES MF 10.0K 1/16W 1% 0402; AGILE_PN: 470-80574; ASSY_OPT: DNP; CAD_APPROVED: Yes; EN: 101-1-00389; FPLIST: RC0402_25,RC0402_HD,0402_CC; HEIGHT: 0.4MM; MFG_NAME01: WALSIN TECHNOLOGY CORP.; MFG_PN01: WR04X1002FTL; ROHS: Yes; Tolerance: 1%
U3 = CS42448-DQ_LQFP64: IC CODEC 6IN 8OUT 108DB 192KHZ 3.14-5.25V AUTO LQFP64; AGILE_PN: 312-81688; CAD_APPROVED: Yes; HEIGHT: 1.6MM; MFG_NAME01: CIRRUS LOGIC; ROHS: Yes; Temp Range: -40°C to +105°C; VOLTAGE: 3.14-5.25V
C37 C38 = CAP_NP: CAP CER 1uF 10V 10% X7S AEC-Q200 0402; AGILE_PN: 150-79497; CAD_APPROVED: Yes; EN: 102-1-02280; FPLIST: CC0402_25,CC0402_HD,0402_CC; HEIGHT: 0.7MM; MFG_NAME01: murata; MFG_PN01: GCM155C71A105KE38D; ROHS: Yes; Tolerance: 10%; VOLTAGE: 10V
C39 C40 = CAP_NP: CAP CER 0.47uF 25V 10% X7R AEC-Q200 0603; AGILE_PN: 150-79465; CAD_APPROVED: Yes; EN: 102-1-00176; FPLIST: CC0603_OV,CC0603,0603_CC; HEIGHT: 0.9MM; MFG_NAME01: TDK; MFG_PN01: CGA3E3X7R1E474K080AB; ROHS: Yes; Tolerance: 10%; VOLTAGE: 25V
C41-C44 = CAP_NP: CAP PPS FILM 0.1uF 16V 2% -- 1210; AGILE_PN: 150-80099; CAD_APPROVED: Yes; FPLIST: CC1210,1210_CC; HEIGHT: 2.3 MM; MFG_NAME01: PANASONIC; MFG_PN01: ECHU1C104GX5; Package Size: 1210; ROHS: Yes; Temp Range: -55° C to +125° C; Tolerance: 2%; VOLTAGE: 16V
C45 C50 C53 C56 C77 C78 = CAP_POL: CAP ALEL 4.7uF 16V 20% -- CASE B AEC-Q200 SMT; AGILE_PN: 150-80138; CAD_APPROVED: Yes; EN: 102-3-00211; HEIGHT: 5.5MM; MFG_NAME01: PANASONIC; MFG_PN01: EEE-1CA4R7NR; ROHS: Yes; TOL: 20%; VOLTAGE: 16V
C47 C49 = CAP_NP: CAP CER 2.2UF 10V 10% X5R 0402; AGILE_PN: 150-79475; CAD_APPROVED: Yes; FPLIST: CC0402_25,CC0402_HD,0402_CC,capc0402_l; HEIGHT: 0.56MM; MFG_NAME01: AVX; MFG_PN01: 0402ZD225KAT2A; Package Size: 0402; ROHS: Yes; Tolerance: 10%; VOLTAGE: 10V
C51 C54 C73 C74 = CAP_POL: CAP ALEL 10UF 16V 20% CASE B; AGILE_PN: 150-76751; CAD_APPROVED: Yes; EN: 102-3-00011; HEIGHT: 5.4MM; MFG_NAME01: PANASONIC; MFG_PN01: EEE1CA100SR; ROHS: Yes; Tolerance: 20%; VOLTAGE: 16V
C52 C55 C59 C60 C63 C64 C67 C68 C71 C72 C75 C76 = CAP_NP: CAP CER 2200pF 50V 5% C0G 0402; AGILE_PN: 150-80808; CAD_APPROVED: Yes; FPLIST: CC0402_25,CC0402_HD,0402_CC,capc0402_l; HEIGHT: 0.55MM; MFG_NAME01: MURATA; MFG_PN01: GRM1555C1H222JA01; Package Size: 0402 (1005M); Package Type: Surface Mount, MLCC; ROHS: Yes; Rated Voltage: 50V; Temp Range: -55 °C to +125 °C; Tolerance: 5%; VOLTAGE: 50V
J6-J12 J15 = CONN_AUDIOJACK_6P: CON 6 AUD JACK RA SMT -- 191H AU; AGILE_PN: 211-79704; CAD_APPROVED: Yes; HEIGHT: 4.85 MM; MFG_NAME01: SHENZHEN ATOM TECHNOLOGY CO.,LTD; ROHS: Yes
P1 P2 = MIC_POM: AUDIO DEVICE MIC 0.5MA 2V 38-48+/-3dB 2.2KOHM 6MM TH; AGILE_PN: 510-77987; CAD_APPROVED: Yes; HEIGHT: 2.4MM; MFG_NAME01: Soberton Inc; ROHS: Yes
R38 R39 = RES: RES MF 2.2K 1/16W 1% 0402; AGILE_PN: 470-78359; CAD_APPROVED: Yes; EN: 101-1-03621; FPLIST: RC0402_25,RC0402_HD,0402_CC; HEIGHT: 0.4MM; MFG_NAME01: KOA SPEER; MFG_PN01: RK73H1ETTP2201F; ROHS: Yes; Tolerance: 1%
R40 R42 = RES: RES MF 150K 1/16W 1% 0402; AGILE_PN: 470-30501; CAD_APPROVED: Yes; EN: 101-1-00502; FPLIST: RC0402_25,RC0402_HD,0402_CC; HEIGHT: 0.4MM; MFG_NAME01: YAGEO AMERICA; MFG_PN01: RC0402FR-07150KL; ROHS: Yes; Tolerance: 1%
R48 R50 R51 R53 R75 R76 R78 R79 = RES: RES MF 2.49K  1/10W 1% AEC-Q200 0402; AGILE_PN: 470-30877; CAD_APPROVED: Yes; EN: 101-1-00331; FPLIST: RC0402_25,RC0402_HD,0402_CC; HEIGHT: 0.40 MM; MFG_NAME01: KOA SPEER; MFG_PN01: RK73H1ETTP2491F; ROHS: Yes; Temp_Range: -55C to +155C; Tolerance: 1%
R84 R85 = RES: RES MF ZERO OHM 1/16W 5% 0402; AGILE_PN: 470-75394; CAD_APPROVED: Yes; FPLIST: RC0402_25,RC0402_HD,RC0402_X2,0402_CC; HEIGHT: 0.45 MM; MFG_NAME01: YAGEO AMERICA; MFG_PN01: RC0402JR-070RL; ROHS: Yes; Tolerance: 5%; VOLTAGE: 1/16W
TP18-TP35 = T_POINT_R: TEST POINT PAD .035 SMT, no part to order; AGILE_PN: 510-75618; CAD_APPROVED: Yes; HEIGHT: 0.1MM; ROHS: Yes
TVS1 TVS4-TVS10 TVS12-TVS17 = DIODE_TVS_BIDIR: DIODE SUPPRESSOR 16A@30NS 5V@1UA SOD-523; AGILE_PN: 480-76937; CAD_APPROVED: Yes; HEIGHT: 0.7MM; MFG_NAME01: on semiconductor; ROHS: Yes
U4 U5 = MAX9814_TDFN14: IC LIN AGC AMP 2.7-5.5V TDFN14; AGILE_PN: 315-79082; CAD_APPROVED: Yes; EN: 301-0-01312; HEIGHT: 0.8MM; MFG_NAME01: MAXIM; ROHS: Yes
C57 C58 C61 C62 C65 C66 C69 C70 = CAP_POL: CAP ALEL 3.3uF 16V 20% -- SMT; AGILE_PN: 150-80137; CAD_APPROVED: Yes; EN: 102-3-00212; HEIGHT: 5.5 MM; MFG_NAME01: WURTH ELEKTRONIK EISOS GMBH & CO. KG; MFG_PN01: 865250340001; ROHS: Yes; TOL: 20%; VOLTAGE: 16V

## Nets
AGND: C18.2 C19.2 C20.2 C21.2 C22.2 C23.2 C24.2 C25.2 C26.2 C32.2 C33.2 C37.2 C38.2 C39.1 C40.1 C45.2 C46.2 C47.2 C48.2 C49.2 C50.2 C52.2 C53.2 C55.2 C56.2 C59.2 C60.2 C63.2 C64.2 C67.2 C68.2 C71.2 C72.2 C75.2 C76.2 C77.2 C78.2 J6.1 J7.1 J8.1 J9.1 J10.1 J11.1 J12.1 J15.1 P1.2(GND) P2.2(GND) R28.2 R33.2 R36.2 R37.2 R41.2 R43.2 R45.2 R47.2 R50.1 R53.1 R56.2 R57.2 R60.2 R61.2 R64.2 R65.2 R68.2 R69.2 R76.1 R79.1 R82.2 TVS1.1(A1) TVS4.1(A1) TVS5.1(A1) TVS6.1(A1) TVS7.1(A1) TVS8.1(A1) TVS9.1(A1) TVS10.1(A1) TVS12.1(A1) TVS13.1(A1) TVS14.1(A1) TVS15.1(A1) TVS16.1(A1) TVS17.1(A1) U3.42(AGND1) U3.56(AGND2) U4.4(NC) U4.7(GND) U4.11(NC) U4.15(EP_PAD) U5.4(NC) U5.7(GND) U5.11(NC) U5.15(EP_PAD)
GND: C1.2 C2.2 C3.2 C4.2 C5.2 C6.2 C7.2 C8.2 C9.2 C10.2 C11.2 C12.2 C14.2 C15.2 C16.2 C17.2 C27.2 C28.2 C29.2 C30.2 C31.2 C34.2 C35.2 C36.2 D1.C(CATHODE) H1.1(NC) H2.1(NC) J1.2(B1) J1.6(B3) J1.14(B7) J1.24(B12) Q2.2(SOURCE) R6.2 R7.2 R23.2 R28.1 R31.2 R32.2 R82.1 TP2.1(Pin1) TP3.1(Pin1) U1.2(GND) U2.1(GND) U3.7(DGND1) U3.23(DGND2) U3.62(DGND3)
P1V8: C3.1 C4.1 J1.8(B4) J4.1
P1V8_S: C16.1 C17.1 J4.3 U2.2(VOUT)
P3V3: C1.1 C2.1 J1.4(B2) J3.1
P3V3_S: C11.1 C12.1 J3.3 J14.1 R3.1 U1.5(OUT)
P5V: C5.1 C6.1 J1.10(B5) J1.12(B6) J2.2 R1.1 R83.1
P5V_S: C7.1 C8.1 C13.2 FB1.1 J13.1 Q1.3(DRAIN) TP4.1(Pin1)
VCC_1V8: J4.2 J5.3 TP6.1(Pin1)
VCC_3V3: FB2.1 J3.2 J5.1 TP5.1(Pin1)
VCC_CODEC_3V3: C27.1 C28.1 C29.1 C30.1 C31.1 FB2.2 U3.6(VD1) U3.24(VD2)
VCC_CODEC_5V0: C18.1 C19.1 C20.1 C21.1 C22.1 C37.1 C38.1 FB1.2 R34.2 R35.2 R44.2 R46.2 U3.44(VA1) U3.53(VA2) U4.2(~{SHDN}) U4.5(VDD) U5.2(~{SHDN}) U5.5(VDD)
VCC_CODEC_IO: C34.1 C35.1 C36.1 FB3.2 R24.2 R25.2 R26.2 R27.2 R29.2 R30.2 U3.4(VLC) U3.8(VLS)
AD0_CS#: R29.1 R31.1 U3.1(AD0/~{CS})
AD1_CDIN: R30.1 R32.1 U3.2(AD1/CDIN)
ADC_LRCK: R11.2 U3.5(ADC_LRCK)
ADC_SCLK: R10.2 U3.9(ADC_SCLK)
ADC_SDOUT1: R12.2 U3.13(ADC_SDOUT1)
ADC_SDOUT2: R14.2 U3.12(ADC_SDOUT2)
ADC_SDOUT3: R81.2 U3.11(ADC_SDOUT3)
AIN_1: J12.3 R48.1 TVS14.2(A2)
AIN_2: J12.2 R51.1 TVS15.2(A2)
AIN_3: J15.3 R75.1 TVS16.2(A2)
AIN_4: J15.2 R78.1 TVS17.2(A2)
AMP1_A/R: R35.1 R36.1 U4.9(A/R)
AMP1_BIAS: C39.2 U4.12(BIAS)
AMP1_CG: C47.1 U4.3(CG)
AMP1_CT: C46.1 U4.1(CT)
AMP1_GAIN_IN: R46.1 R47.1 U4.10(GAIN)
AMP1_MIC_IN: C41.2 U4.8(MICIN)
AMP1_MICBIAS: R38.2 R42.2 U4.13(MICBIAS)
AMP1_MICOUT: C42.1 U4.6(MICOUT)
AMP1_TH_IN: R42.1 R43.1 U4.14(TH)
AMP2_A/R: R34.1 R37.1 U5.9(A/R)
AMP2_BIAS: C40.2 U5.12(BIAS)
AMP2_CG: C49.1 U5.3(CG)
AMP2_CT: C48.1 U5.1(CT)
AMP2_GAIN_IN: R44.1 R45.1 U5.10(GAIN)
AMP2_MIC_IN: C43.2 U5.8(MICIN)
AMP2_MICBIAS: R39.2 R40.2 U5.13(MICBIAS)
AMP2_MICOUT: C44.1 U5.6(MICOUT)
AMP2_TH_IN: R40.1 R41.1 U5.14(TH)
AOUT_1: C59.1 J6.3 R54.2 TVS4.2(A2)
AOUT_2: C63.1 J6.2 R58.2 TVS1.2(A2)
AOUT_3: C67.1 J7.3 R62.2 TVS5.2(A2)
AOUT_4: C71.1 J7.2 R66.2 TVS6.2(A2)
AOUT_5: C60.1 J8.3 R55.2 TVS7.2(A2)
AOUT_6: C64.1 J8.2 R59.2 TVS8.2(A2)
AOUT_7: C68.1 J9.3 R63.2 TVS9.2(A2)
AOUT_8: C72.1 J9.2 R67.2 TVS10.2(A2)
AUX_LRCK: TP16.1(Pin1) U3.20(AUX_LRCK)
AUX_SCLK: TP14.1(Pin1) U3.21(AUX_SCLK)
AUX_SDIN: R23.1 TP36.1(Pin1) U3.22(AUX_SDIN)
CODEC_AOUT1_P: C57.1 U3.26(AOUT1+)
CODEC_AOUT2_P: C61.1 U3.27(AOUT2+)
CODEC_AOUT3_P: C65.1 U3.30(AOUT3+)
CODEC_AOUT4_P: C69.1 U3.31(AOUT4+)
CODEC_AOUT5_P: C58.1 U3.34(AOUT5+)
CODEC_AOUT6_P: C62.1 U3.36(AOUT6+)
CODEC_AOUT7_P: C66.1 U3.39(AOUT7+)
CODEC_AOUT8_P: C70.1 U3.40(AOUT8+)
CODEC_AUX_IN1_N: C53.1 U3.45(AIN1-)
CODEC_AUX_IN1_P: C51.1 C52.1 U3.46(AIN1+)
CODEC_AUX_IN2_N: C56.1 U3.47(AIN2-)
CODEC_AUX_IN2_P: C54.1 C55.1 U3.48(AIN2+)
CODEC_AUX_IN3_N: C77.1 U3.49(AIN3-)
CODEC_AUX_IN3_P: C73.1 C75.1 U3.50(AIN3+)
CODEC_AUX_IN4_N: C78.1 U3.51(AIN4-)
CODEC_AUX_IN4_P: C74.1 C76.1 U3.52(AIN4+)
CODEC_MIC1_N: C50.1 U3.58(AIN5+/AIN5A)
CODEC_MIC1_P: C42.2 U3.57(AIN5-/AIN5B)
CODEC_MIC2_N: C45.1 U3.60(AIN6+/AIN6A)
CODEC_MIC2_P: C44.2 U3.59(AIN6-/AIN6B)
DAC_LRCK: R16.2 U3.19(DAC_LRCK)
DAC_SCLK: R15.2 U3.18(DAC_SCLK)
DAC_SDIN1: R17.2 U3.17(DAC_SDIN1)
DAC_SDIN2: R18.2 U3.16(DAC_SDIN2)
DAC_SDIN3: R19.2 U3.15(DAC_SDIN3)
DAC_SDIN4: R20.2 U3.14(DAC_SDIN4)
DC_GPIO1: J1.21(A11) R4.1
DC_I2C_SCL: J1.13(A7) R21.1 R25.1
DC_I2C_SDA: J1.15(A8) R22.1 R27.1
DC_I2S1_MCLK: J1.1(A1) R9.1
DC_I2S1_RX_BCLK: J1.5(A3) R10.1
DC_I2S1_RX_D0: J1.11(A6) R12.1
DC_I2S1_RX_SYNC: J1.9(A5) R11.1
DC_I2S1_TX_BCLK: J1.23(A12) R15.1
DC_I2S1_TX_D0: J1.17(A9) R17.1
DC_I2S1_TX_D1: J1.18(B9) R14.1 R18.1
DC_I2S1_TX_D2: J1.19(A10) R19.1 R81.1
DC_I2S1_TX_D3: J1.20(B10) R20.1
DC_I2S1_TX_SYNC: J1.16(B8) R16.1
DC_INT: J1.3(A2) R24.1 U3.61(INT)
DC_RESET: J1.7(A4) R26.1 U3.3(~{RST})
MCLK_IN: R9.2 U3.10(MCLK)
MICIN_1: C41.1 J10.4 R38.1 R71.1 R72.1 R84.2 TVS12.2(A2)
MICIN_2: C43.1 J11.4 R39.1 R73.1 R74.1 R85.2 TVS13.2(A2)
MUTEC_OUT: R33.1 TP17.1(Pin1) U3.35(MUTEC)
SCL_CCLK: R21.2 U3.63(SCL/CCLK)
SDA_CDOUT: R22.2 U3.64(SDA/CDOUT)
N16325068: FB3.1 J5.2
N16325522: TP9.1(Pin1) U3.25(AOUT1-)
N16325540: TP10.1(Pin1) U3.28(AOUT2-)
N16325558: TP7.1(Pin1) U3.29(AOUT3-)
N16325576: TP8.1(Pin1) U3.32(AOUT4-)
N16325594: TP11.1(Pin1) U3.33(AOUT5-)
N16325612: TP12.1(Pin1) U3.37(AOUT6-)
N16325620: TP13.1(Pin1) U3.38(AOUT7-)
N16325628: TP15.1(Pin1) U3.41(AOUT8-)
N16325638: C25.1 C26.1 U3.55(FILT+_ADC)
N16325678: C32.1 C33.1 U3.54(FILT+_DAC)
N16325718: C23.1 C24.1 U3.43(VQ)
N16334310: R48.2 R49.1 R50.2
N16334338: C51.2 R49.2
N16334434: R51.2 R52.1 R53.2
N16334446: C54.2 R52.2
N16339295: C61.2 R58.1 R60.1
N16339361: C65.2 R62.1 R64.1
N16339413: C58.2 R55.1 R57.1
N16339465: C62.2 R59.1 R61.1
N16339521: C66.2 R63.1 R65.1
N16339573: C57.2 R54.1 R56.1
N16343600: D1.A(ANODE) R1.2
N16357095: Q2.1(GATE) R4.2 R7.1 R83.2
N16357107: Q2.3(DRAIN) R2.2 R5.1
N16357127: J2.1 Q1.2(SOURCE) R2.1
N16357135: C13.1 Q1.1(GATE) R5.2
N16357758: R3.2 R6.1 U1.4(FB)
N16357876: C9.1 C10.1 J13.2 U1.1(IN) U1.3(~{SHDN})
N16358335: C14.1 C15.1 J14.2 U2.3(VIN)
N16404329: C69.2 R66.1 R68.1
N16404657: C70.2 R67.1 R69.1
N16406078: J1.22(B11) TP1.1(Pin1)
N16452852: J10.2 R72.2
N16452871: J10.3 R71.2
N16456970: J6.5 TP18.1(TP)
N16456974: J6.6 TP19.1(TP)
N16456978: J6.4 TP20.1(TP)
N16457195: J7.5 TP21.1(TP)
N16457199: J7.6 TP22.1(TP)
N16457203: J7.4 TP23.1(TP)
N16457422: J8.5 TP24.1(TP)
N16457426: J8.6 TP25.1(TP)
N16457430: J8.4 TP26.1(TP)
N16457651: J9.5 TP27.1(TP)
N16457655: J9.6 TP28.1(TP)
N16457659: J9.4 TP29.1(TP)
N16458067: J12.4 TP32.1(TP)
N16458071: J12.6 TP31.1(TP)
N16458075: J12.5 TP30.1(TP)
N16458447: J11.3 R74.2
N16458491: J11.2 R73.2
N16475768: R75.2 R76.2 R77.1
N16475784: C73.2 R77.2
N16475838: R78.2 R79.2 R80.1
N16475850: C74.2 R80.2
N16477331: J15.4 TP35.1(TP)
N16477335: J15.6 TP34.1(TP)
N16477339: J15.5 TP33.1(TP)
N16544253: P1.1(Out) R84.1
N16544784: P2.1(Out) R85.1

Not connected (* = marked no-connect by the designer): J10 5* 6*; J11 5* 6*

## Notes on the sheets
sheet 1
- AUD-EXP-42448
- Table of Content
- Revision History
- Page 1
- COVER
- Rev. Code
- Date
- By
- Description
- Page 2
- BLOCK DIAGRAM
- A
- 2021-01-06
- Shawn Shi
- Initial Release
- Page 3
- POWER&INTERFACE
- 1. Add R83(DNP) for 3V3 power option
  2. Add P1/P2, R84/R85 for MIC input
  3. Populate R82, DNP R28 for DGND/AGND connection
- B
- 2021-03-26
- Shawn Shi
- Page 4
- AUDIO CODEC
- Page 5
- AUDIO INPUT
- Page 6
- AUDIO OUTPUT
- Page 7
- Page 8
- Page 9
- Page 10
- Page 11
- Page 12
- Page 13
- Page 14
- Page 15
- Page 16
- Page 17
- Page 18
- Page 19
- Page 20
- Page 21
- Page 22
- Page 23
- Page 24
- Page 25
- Page 26
- REF DES
- JUMPER(DEFAULT)
- PAGE NAME
- J13,J14,J2
- 1-2
- 03 POWER&INTERFACE
- J4,J3
- 2-3
- Page 26
- 03 POWER&INTERFACE
- J5
- 1-2
- 04 AUDIO CODEC
- Page 27
- Page 28
- 3. Device type number is for reference only. The number
  varies with the manufacturer.
- 1. Unless Otherwise Specified:
- All resistors are in ohms, 1/16 Watt,0402
- 4. Special signal usage:
- All capacitors are in uF,0402
- _B Denotes - Active-Low Signal
- All voltages are DC
- <> or [] Denotes - Vectored Signals
- All polarized capacitors are aluminum electrolytic
- 5. Interpret diagram in accordance with American
  National Standards Institute specifications, current
  revision, with the exception of logic block symbology.
- 2. Interrupted lines coded with the same letter or letter
      combinations are electrically connected.
sheet 2
- AUD-EXP-42448
- #####  Blcok Diagram Rev B#####
sheet 3
- Audio Main CONN
- DC_SAI1_MCLK
- DC_INT
- DC_SAI1_RX_BCLK
- DC_3V3(Opt)
- DC_RESET
- DC_1V8(Opt)
- DC_SAI1_RX_SYNC
- DC_SAI1_RXD0
- DC_5V
- DC_I2C_SCL
- DC_I2C_SDA
- DC_SAI1_TX_SYNC
- DC_I2S1_TX_D0
- DC_I2S1_TX_D2
- DC_I2S1_TX_D1
- DC_I2S1_TX_D3
- DC_GPIO1
- DC_GPIO2
- DC_SAI1_TX_BCLK
- 5V Control
- 3V3 LDO
- Default: 1-2
- MAX 350mA
- Default: 1-2
- Vfb=1V
- 1-->>Enable
  0-->>Disable
- 1V8 LDO
- Power Options
- MAX 250mA
- Default: 1-2
- Default: 2-3
- Default: 2-3
- Standoff Mounting Holes
- Test Points
sheet 4
- Audio Codec
- Audio Codec Power&GND
- P53
- P44
- P53
- P44
- P24
- P6
- P24
- P6
- Note:RT TXD1/TXD2 can be configured as RXD
- P4
- P8
- Default: 1-2
- I2C Address Config
sheet 5
- Audio Input Amplifiers
- CCT
- CCT
- Auxiliary Audio Input Filter
- Input TRS Connectors
- MIC1 INPUT
- MIC2 INPUT
- Stereo INPUT1
- Stereo INPUT2
sheet 6
- Audio Output Filters
- Output TRS Connectors
- LINE1&LINE2 OUTPUT
- LINE3&LINE4 OUTPUT
- LINE5&LINE6 OUTPUT
- LINE7&LINE8 OUTPUT
